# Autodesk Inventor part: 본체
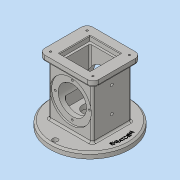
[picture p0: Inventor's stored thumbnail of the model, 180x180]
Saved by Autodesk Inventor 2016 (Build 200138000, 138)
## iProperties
Created: 2019-08
Part Number: 본체
Material: 일반
Document SubType Name: Modeling
Designer: Administrator
Density: 1 g/cm^3
Appearance: 기본값
Mass: 384.297 g
Surface Area: 786.762 cm^2
Volume: 384.297 cm^3
Author: Administrator
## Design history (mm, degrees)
sketch "스케치1"
  geometry: L1 (37, 33)-(-37, 33); L2 (-37, 33)-(-37, -33); L3 (-37, -33)-(37, -33); L4 (37, -33)-(37, 33); L5 (37, 33)-(-37, -33); L6 (-37, 33)-(37, -33); 1 further point
  constraints: 12 end point, 2 midpoint, 2 parallel, 1 horizontal, 1 perpendicular
  dimensions: "d0" = 66 distance of L3.end L1.start; "d1" = 74 distance of L2.end L3.end
extrude "돌출1" new body sketch "스케치1" stored distance "d2" = 88; taper "d3" = 0 deg
sketch "스케치2"
  geometry: L1 (-37, -33)-(37, -33) reference; L2 (37, -33)-(37, 33) reference; L3 (37, 33)-(-37, 33) reference; L4 (-37, 33)-(-37, -33) reference; L5 (-46, -41)-(46, -41); L6 (46, -41)-(46, 41); L7 (46, 41)-(-46, 41); L8 (-46, 41)-(-46, -41); L9 (-46, -41)-(46, 41); L10 (46, -41)-(-46, 41); 1 further point
  constraints: 12 end point, 2 midpoint, 2 parallel, 1 horizontal, 1 perpendicular
  dimensions: "d4" = 82 distance of L7.end L5.start; "d5" = 92 distance of L6.end L7.end
extrude "돌출2" join sketch "스케치2" distance "d6" = 10; taper "d7" = 0 deg
sketch "스케치3"
  geometry: L1 (37, 33)-(-37, 33) reference; L2 (-37, 33)-(-37, -33) reference; L3 (-37, -33)-(37, -33) reference; L4 (37, -33)-(37, 33) reference; C1 r 67.5 at (0, 0); 1 further point
  constraints: 1 centre point, 1 coincident
  dimensions: "d8" = 135 diameter of C1
extrude "돌출3" join sketch "스케치3" distance "d9" = 10; taper "d10" = 0 deg
sketch "스케치4"
  geometry: L1 (44, 33)-(-44, 33) reference; L2 (0, 33)-(35, 33); L3 (35, 33)-(35, 30); L4 (35, 30)-(0, 30); L5 (0, 30)-(0, 33); L6 (0, 30)-(24, 30); L7 (24, 30)-(24, -30); L8 (24, -30)-(0, -30); L9 (0, -30)-(0, 30); L10 (-44, -33)-(44, -33) reference; L11 (0, -30)-(35, -30); L12 (35, -30)-(35, -33); L13 (35, -33)-(0, -33); L14 (0, -33)-(0, -30); 1 further point
  constraints: 24 end point, 6 parallel, 3 horizontal, 3 perpendicular, 1 midpoint, 1 point on line
  dimensions: "d11" = 70 diameter of L3 L5; "d12" = 48 diameter of L7 L9; "d13" = 70 diameter of L12 L14; "d14" = 3 distance of L2.end L3.end; "d15" = 3 distance of L11.end L12.end
revolve "회전1" sketch "스케치4" stored, may be unused: angle "d16" = 90 deg
sketch "스케치5" dims "d17" = 58
  geometry: C1 r 24 at (0, 0) reference; 3 further points
  constraints: 1 coincident, 1 vertical alignment, 2 other
hole "구멍1" sketch "스케치5" at (0, 29) diameter "d18" = 3.242; stored, may be unused: countersink angle "d22" = 90 deg, drill point angle "d24" = 118 deg; dims "d19" = 4, "d20" = 4, "d21" = 2, "d23" = 6
sketch "스케치6"
  geometry: L1 (-26, 26)-(26, 26); L2 (26, 26)-(26, -26); L3 (26, -26)-(-26, -26); L4 (-26, -26)-(-26, 26); L5 (-26, 26)-(26, -26); L6 (26, 26)-(-26, -26); 1 further point
  constraints: 12 end point, 2 midpoint, 2 parallel, 1 horizontal, 1 perpendicular
  dimensions: "d28" = 52 distance of L1.start L1.end; "d29" = 52 distance of L1.end L2.end
extrude "돌출4" cut sketch "스케치6" distance "d30" = 8; taper "d31" = 0 deg
sketch "스케치7"
  geometry: L1 (-22, 22)-(22, 22); L2 (22, 22)-(22, -22); L3 (22, -22)-(-22, -22); L4 (-22, -22)-(-22, 22); L5 (-22, 22)-(22, -22); L6 (22, 22)-(-22, -22); 1 further point
  constraints: 12 end point, 2 midpoint, 2 parallel, 1 horizontal, 1 perpendicular
  dimensions: "d32" = 44 distance of L1.start L1.end; "d33" = 44 distance of L1.end L2.end
extrude "돌출5" cut sketch "스케치7" distance "d34" = 74; taper "d35" = 0 deg
sketch "스케치8"
  geometry: C1 r 25 at (0, 0); 1 further point
  constraints: 1 centre point, 1 coincident
  dimensions: "d36" = 50 diameter of C1
extrude "돌출6" cut sketch "스케치8" distance "d37" = 18; taper "d38" = 0 deg
sketch "스케치9"
  geometry: C1 r 12.5 at (0, 0); 1 further point
  constraints: 1 centre point, 1 coincident
  dimensions: "d39" = 25 diameter of C1
extrude "돌출7" cut sketch "스케치9" distance "d40" = 30; taper "d41" = 0 deg
sketch "스케치10"
  geometry: L1 (58, -98)-(8, -98) reference; L2 (59, 10)-(7, 10) reference; 3 further points
  dimensions: "d42" = 37 distance from line of L1 point (33, -61); "d43" = 43 distance of point (33, -18) point (33, -61)
hole "구멍2" sketch "스케치10" at (33, -61), (33, -18) diameter "d44" = 4.917; stored, may be unused: countersink angle "d48" = 90 deg, drill point angle "d50" = 118 deg; dims "d45" = 25, "d46" = 4, "d47" = 2, "d49" = 30
sketch "스케치11"
  geometry: L1 (46, 41)-(-46, 41) reference; L2 (-22, 22)-(22, 22) reference; L3 (-22, -22)-(-22, 22) reference; L4 (22, -22)-(-22, -22) reference; L5 (22, 22)-(22, -22) reference; L6 (-36, 31)-(36, 31); L7 (36, 31)-(36, -31); L8 (36, -31)-(-36, -31); L9 (-36, -31)-(-36, 31); L10 (-36, 31)-(36, -31); L11 (36, 31)-(-36, -31); L12 (35, 30)-(35, 33) reference; C1 r 12.5 at (0, 0) reference; 5 further points
  constraints: 12 end point, 4 coincident, 2 midpoint, 2 parallel, 1 horizontal, 1 perpendicular
  dimensions: "d51" = 62 distance of L6.end L7.end; "d52" = 72 distance of L6.start L6.end
hole "구멍3" sketch "스케치11" at (-36, 31), (36, -31), (-36, -31), (36, 31) diameter "d53" = 3.242; stored, may be unused: countersink angle "d57" = 90 deg, drill point angle "d59" = 118 deg; dims "d54" = 4, "d55" = 4, "d56" = 2, "d58" = 6
sketch "스케치12"
  geometry: C1 r 4.5 at (0, 59); C2 r 4.5 at (-59, 0); C3 r 4.5 at (0, -59); 1 further point
  constraints: 3 centre point
  dimensions: "d61" = 9 diameter of C1; "d62" = 9 diameter of C2; "d63" = 9 diameter of C3
extrude "돌출8" cut sketch "스케치12" stored distance "d64" = 30; taper "d65" = 0 deg
sketch "스케치13"
  geometry: C1 r 59 at (0, 0); 1 further point
  constraints: 1 centre point, 1 coincident, 1 other
  dimensions: "d66" = 118 diameter of C1
feature "엠보싱1" sketch "스케치13" dims "d0" = 66, "d1" = 74, "d67" = 0.5, "d68" = 0
fillet "모깎기1" dims "d69" = 10
chamfer "모따기1" distance "d70" = 3; stored, may be unused: second distance "d71" = 2, angle "d72" = 45 deg
chamfer "모따기2" distance "d73" = 1; stored, may be unused: second distance "d74" = 2, angle "d75" = 45 deg
fillet "모깎기2" dims "d76" = 3
fillet "모깎기3" dims "d77" = 3
node "솔리드1"
pattern_circular "원형 패턴1" dims angle "d26" = 360 deg
mirror "대칭1"
node "투영된 루프1"
node "투영된 루프2"
node "투영된 루프3"
